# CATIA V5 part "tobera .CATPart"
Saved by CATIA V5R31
Part number: tobera 
Bounding box of the stored display mesh (mm): x -57.25 to 57.25, y -64.471 to 64.471, z 0 to 85
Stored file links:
  C:\Users\189361\Desktop\piezas del comedero\piezas del comedero\tobera .CATPart
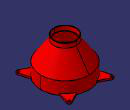
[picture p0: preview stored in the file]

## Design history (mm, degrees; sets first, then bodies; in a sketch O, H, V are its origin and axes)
Body1 (main body)
  Sketch1 on xy-plane, origin (0, 0, 0), H (1, 0, 0), V (0, 1, 0)
    circle A1 centre (0, 0) radius 55.25
    circle A2 centre (0, 0) radius 57.25
    radius A1 = 55.25
    radius A2 = 57.25
  Pad1: profile Sketch1, direction (0, 0, 1), length 30
  Sketch2 on yz-plane, origin (0, 0, 0), H (0, 1, 0), V (0, 0, 1)
    construction line L1 (0, 75) -> (23.15, 75)
    point P1 (0, 75)
    point P2 (23.15, 75)
    construction line L2 (0, 30) -> (55.25, 30)
    point P3 (0, 30)
    reference projected line E1 (-55.25, 30) -> (55.25, 30) from edge [end face of Pad1 | face of Pad1 from Sketch1.A1]
    construction line L3 (0, 30) -> (57.25, 30)
    point P5 (0, 30)
    construction line L4 (0, 75) -> (26.65, 75)
    line L5 (55.25, 30) -> (57.25, 30)
    line L6 (57.25, 30) -> (26.65, 75)
    line L7 (55.25, 30) -> (23.15, 75)
    line L8 (23.15, 75) -> (25.15, 75)
    point P8 (23.15, 75)
    line L9 (25.15, 75) -> (25.15, 85)
    line L10 (25.15, 85) -> (26.65, 85)
    line L11 (26.65, 85) -> (26.65, 75)
    length L2 = 55.25
    length L3 = 57.25
    length L4 = 26.65
    distance L3 L4 = 45
    length L8 = 2
    length L11 = 10
    distance L9 P1 = 25.15
    coincidence: P1 V, P3 V, E1 L2, P5 V, L3 L2, P8 L7, P8 L4, P2 P8
    horizontal: L1 H, L2 H, L3 H, L4 H, L5 H, L8 H, L10 H
    vertical: L9 V, L11 V
  Shaft1: profile Sketch2, axis axis of face of Pad1 from Sketch1.A2, angle 360
  Sketch3 on start face of Pad1, origin (0, 0, 0), H (1, 0, 0), V (0, -1, 0)
    circle A1 centre (50, 60) radius 2.25
    point P1 (50, 60)
    arc A2 centre (0, 0) radius 57.25 from (46.7848, 32.9962) to (36.6506, 43.9807) ccw
    point P2 (46.7848, 32.9962)
    point P3 (36.6506, 43.9807)
    arc A3 centre (50, 60) radius 4.5 from (54.3188, 58.7359) to (47.9778, 64.02) ccw
    construction line L1 (0, 0) -> (50, 60)
    line L2 (46.7848, 32.9962) -> (54.3188, 58.7359)
    point P4 (54.3188, 58.7359)
    axis line L3 (0, 0) -> (46.7848, 32.9962)
    point P5 (0, 0)
    point P6 (46.7848, 32.9962)
    reference projected circle E1 centre (0, 0) radius 57.25 from edge [start face of Pad1 | face of Pad1 from Sketch1.A2]
    point P7 (36.6506, 43.9807)
    point P8 (24.0187, 51.9679)
    arc A4 centre (0, 0) radius 57.25 from (24.0187, 51.9679) to (36.6506, 43.9807) cw
    point P10 (47.9778, 64.02)
    line L4 (24.0187, 51.9679) -> (47.9778, 64.02)
    point P12 (-46.7848, 32.9962)
    point P13 (-36.6506, 43.9807)
    point P14 (-54.3188, 58.7359)
    point P15 (-46.7848, 32.9962)
    point P16 (-36.6506, 43.9807)
    point P17 (-24.0187, 51.9679)
    point P18 (-47.9778, 64.02)
    circle A5 centre (-50, 60) radius 2.25
    arc A6 centre (0, 0) radius 57.25 from (-46.7848, 32.9962) to (-36.6506, 43.9807) cw
    arc A7 centre (-50, 60) radius 4.5 from (-54.3188, 58.7359) to (-47.9778, 64.02) cw
    line L5 (-46.7848, 32.9962) -> (-54.3188, 58.7359)
    arc A8 centre (0, 0) radius 57.25 from (-24.0187, 51.9679) to (-36.6506, 43.9807) ccw
    line L6 (-24.0187, 51.9679) -> (-47.9778, 64.02)
    point P22 (46.7848, -32.9962)
    point P23 (36.6506, -43.9807)
    point P24 (54.3188, -58.7359)
    point P25 (46.7848, -32.9962)
    point P26 (36.6506, -43.9807)
    point P27 (24.0187, -51.9679)
    point P28 (47.9778, -64.02)
    point P30 (-46.7848, -32.9962)
    point P31 (-36.6506, -43.9807)
    point P32 (-54.3188, -58.7359)
    point P33 (-46.7848, -32.9962)
    point P34 (-36.6506, -43.9807)
    point P35 (-24.0187, -51.9679)
    point P36 (-47.9778, -64.02)
    circle A9 centre (50, -60) radius 2.25
    arc A10 centre (0, 0) radius 57.25 from (46.7848, -32.9962) to (36.6506, -43.9807) cw
    arc A11 centre (50, -60) radius 4.5 from (54.3188, -58.7359) to (47.9778, -64.02) cw
    line L7 (46.7848, -32.9962) -> (54.3188, -58.7359)
    arc A12 centre (0, 0) radius 57.25 from (24.0187, -51.9679) to (36.6506, -43.9807) ccw
    line L8 (24.0187, -51.9679) -> (47.9778, -64.02)
    circle A13 centre (-50, -60) radius 2.25
    arc A14 centre (0, 0) radius 57.25 from (-46.7848, -32.9962) to (-36.6506, -43.9807) ccw
    arc A15 centre (-50, -60) radius 4.5 from (-54.3188, -58.7359) to (-47.9778, -64.02) ccw
    line L9 (-46.7848, -32.9962) -> (-54.3188, -58.7359)
    arc A16 centre (0, 0) radius 57.25 from (-24.0187, -51.9679) to (-36.6506, -43.9807) cw
    line L10 (-24.0187, -51.9679) -> (-47.9778, -64.02)
    radius A1 = 2.25
    distance H P1 = 60
    distance V P1 = 50
    radius A3 = 4.5
    angle L1 L3 = 15
    coincidence: P3 L1, P5 L1, P5 V, L3 P2, A2 E1, P6 P2, P3 P7, P13 P16, P23 P26, P31 P34
    tangency: L2 A3
    concentricity: A2 E1
    symmetry: P3 P7 L1, P2 P8 L1, A2 A4 L1, P4 P10 L1, L2 L4 L1, P2 P12 V, P3 P13 V, P4 P14 V, P6 P15 V, P7 P16 V, P8 P17 V, P10 P18 V, A1 A5 V, A2 A6 V, A3 A7 V, L2 L5 V, A4 A8 V, L4 L6 V, P2 P22 H, P3 P23 H, P4 P24 H, P6 P25 H, P7 P26 H, P8 P27 H, P10 P28 H, P12 P30 H, P13 P31 H, P14 P32 H, P15 P33 H, P16 P34 H, P17 P35 H, P18 P36 H, A1 A9 H, A2 A10 H, A3 A11 H, L2 L7 H, A4 A12 H, L4 L8 H, A5 A13 H, A6 A14 H, A7 A15 H, L5 L9 H, A8 A16 H, L6 L10 H
  Pad2: profile Sketch3, direction (0, 0, 1), length 4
